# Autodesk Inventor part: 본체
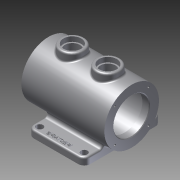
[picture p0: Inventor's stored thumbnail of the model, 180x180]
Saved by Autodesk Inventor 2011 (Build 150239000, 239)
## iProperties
Created: 2014-12
Part Number: 본체
Document SubType Name: Modeling
Designer: user
Density: 1 g/cm^3
Author: user
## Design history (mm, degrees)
sketch "스케치1"
  geometry: L1 (-47.5, 65)-(47.5, 65); L2 (47.5, 65)-(47.5, -65); L3 (47.5, -65)-(-47.5, -65); L4 (-47.5, -65)-(-47.5, 65); 3 further points
  constraints: 8 end point, 2 midpoint, 2 parallel, 1 horizontal, 1 horizontal alignment, 1 perpendicular, 1 vertical alignment
  dimensions: "d0" = 95 distance of L1.start L1.end; "d1" = 130 distance of L1.end L2.end
extrude "돌출1" new body sketch "스케치1" distance "d2" = 12; taper "d3" = 0 deg
sketch "스케치2"
  geometry: L1 (47.5, 12)-(47.5, 0) reference; L2 (47.5, 0)-(-47.5, 0) reference; L3 (-47.5, 0)-(-47.5, 12) reference; L4 (-47.5, 12)-(47.5, 12) reference; L5 (77.5, 50)-(-62.5, 50); L6 (77.5, 80)-(65.5, 80); L7 (65.5, 80)-(65.5, 87.5); L8 (65.5, 87.5)-(-50.5, 87.5); L9 (-50.5, 87.5)-(-50.5, 80); L10 (-50.5, 80)-(-62.5, 80); L11 (-62.5, 80)-(-62.5, 96); L12 (-62.5, 96)-(77.5, 96); L13 (77.5, 96)-(77.5, 80); 3 further points
  constraints: 18 end point, 7 parallel, 2 midpoint, 2 vertical alignment, 1 collinear, 1 perpendicular
  dimensions: "d4" = 50 distance between parallel lines of L2 L5; "d5" = 140 distance of L5.start L5.end; "d6" = 15 horizontal distance of L5.end L2.end; "d7" = 92 diameter of L12 L5; "d8" = 60 diameter of L6 L5; "d9" = 60 diameter of L10 L5; "d10" = 75 diameter of L8 L5; "d11" = 12 distance of L6.start L6.end; "d12" = 12 distance of L9.end L10.end
revolve "회전1" sketch "스케치2" stored, may be unused: angle "d13" = 90 deg
node "작업 평면1"
sketch "스케치3"
  geometry: L1 (62.5, 46)-(62.5, -46) reference; L2 (62.5, 46)-(-77.5, 46) reference; L3 (62.5, -46)-(-77.5, -46) reference; L4 (-77.5, 46)-(-77.5, -46) reference; C1 r 20 at (22.5, 0); C2 r 20 at (-37.5, 0); 2 further points
  constraints: 2 centre point, 2 horizontal alignment, 1 equal radius, 1 midpoint
  dimensions: "d15" = 40 distance from line of L1 C1.centre; "d16" = 40 distance from line of C2.centre L4; "d17" = 40 diameter of C1
extrude "돌출2" join sketch "스케치3" stored distance "d18" = 12; taper "d19" = 0 deg
hole "Hole1" diameter "d22" = 25; stored, may be unused: countersink angle "d26" = 90 deg, drill point angle "d28" = 118 deg; dims "d20" = 10, "d21" = 10, "d23" = 6, "d24" = 30, "d25" = 8, "d27" = 8
hole "Hole2" diameter "d31" = 25; stored, may be unused: countersink angle "d35" = 90 deg, drill point angle "d37" = 118 deg; dims "d29" = 10, "d30" = 10, "d32" = 6, "d33" = 30, "d34" = 8, "d36" = 8
sketch "스케치4" dims "d38" = 80
  geometry: L1 (0, 0)-(28.284, -28.284); L2 (0, 0)-(100.104, 0); C1 r 46 at (0, 0) reference; 1 further point
  constraints: 4 end point, 1 coincident, 1 horizontal, 3 other
  dimensions: "d39" = 45 deg angle of L1 L2
hole "Hole3" sketch "스케치4" at (28.284, -28.284) diameter "d40" = 3.242; stored, may be unused: countersink angle "d44" = 90 deg, drill point angle "d46" = 118 deg; dims "d41" = 8, "d42" = 4, "d43" = 2, "d45" = 10
sketch "스케치5" dims "d50" = 80
  geometry: L1 (0, 0)-(-28.284, 28.284); L2 (0, 0)-(-68.814, 0); C1 r 46 at (0, 0) reference; C2 r 30 at (0, 0) reference; 1 further point
  constraints: 4 end point, 2 coincident, 1 horizontal, 3 other
  dimensions: "d51" = 45 deg angle of L1 L2
hole "Hole4" sketch "스케치5" at (-28.284, 28.284) diameter "d52" = 3.242; stored, may be unused: countersink angle "d56" = 90 deg, drill point angle "d58" = 118 deg; dims "d53" = 8, "d54" = 4, "d55" = 2, "d57" = 10
fillet "모깎기1" dims "d62" = 5
fillet "모깎기2" dims "d63" = 3
chamfer "모따기1" distance "d64" = 1; stored, may be unused: second distance "d65" = 2, angle "d66" = 45 deg
chamfer "모따기2" distance "d67" = 1; stored, may be unused: second distance "d68" = 2, angle "d69" = 45 deg
fillet "모깎기3" dims "d70" = 10
fillet "모깎기4" dims "d71" = 3
fillet "모깎기5" dims "d72" = 3
fillet "모깎기6" dims "d73" = 3
fillet "모깎기7" dims "d74" = 3
sketch "스케치6"
  geometry: A1 r 7 centre (-37.5, -55) between (-44.5, -55) and (-37.5, -62) reference; A2 r 7 centre (37.5, -55) between (37.5, -62) and (44.5, -55) reference; 1 further point
hole "Hole5" sketch "스케치6" at (-37.5, -55), (37.5, -55) diameter "d75" = 11; stored, may be unused: countersink angle "d79" = 90 deg, drill point angle "d81" = 118 deg; dims "d76" = 8, "d77" = 4, "d78" = 2, "d80" = 10
sketch "스케치7"
  geometry: A1 r 7 centre (37.5, 55) between (44.5, 55) and (37.5, 62) reference; A2 r 7 centre (-37.5, 55) between (-37.5, 62) and (-44.5, 55) reference; 1 further point
hole "Hole6" sketch "스케치7" at (-37.5, 55), (37.5, 55) diameter "d82" = 11; stored, may be unused: countersink angle "d86" = 90 deg, drill point angle "d88" = 118 deg; dims "d83" = 8, "d84" = 4, "d85" = 2, "d87" = 10
sketch "스케치8"
  geometry: L1 (-23.239, -53.998)-(18.239, -53.998); L2 (18.239, -53.998)-(18.239, -60.002); L3 (18.239, -60.002)-(-23.239, -60.002); L4 (-23.239, -60.002)-(-23.239, -53.998); L5 (-23.239, -57)-(18.239, -57); L6 (-2.5, -60.002)-(-2.5, -53.998); L7 (-37.5, -65)-(37.5, -65) reference; C1 r 5.5 at (-37.5, -55) reference; 2 further points
  constraints: 5 midpoint, 4 end point, 2 other
  dimensions: "d89" = 8 distance from line of L7 point (-2.5, -57); "d90" = 35 horizontal distance of C1.centre point (-2.5, -57)
feature "엠보싱1" sketch "스케치8" dims "d0" = 95, "d1" = 130, "d91" = 1, "d92" = 0
node "솔리드1"
pattern_circular "원형 패턴1" dims angle "d48" = 360 deg
pattern_circular "원형 패턴2" dims angle "d60" = 360 deg
node "절단 모서리 투영1"
other parameters: "d14" = 106
